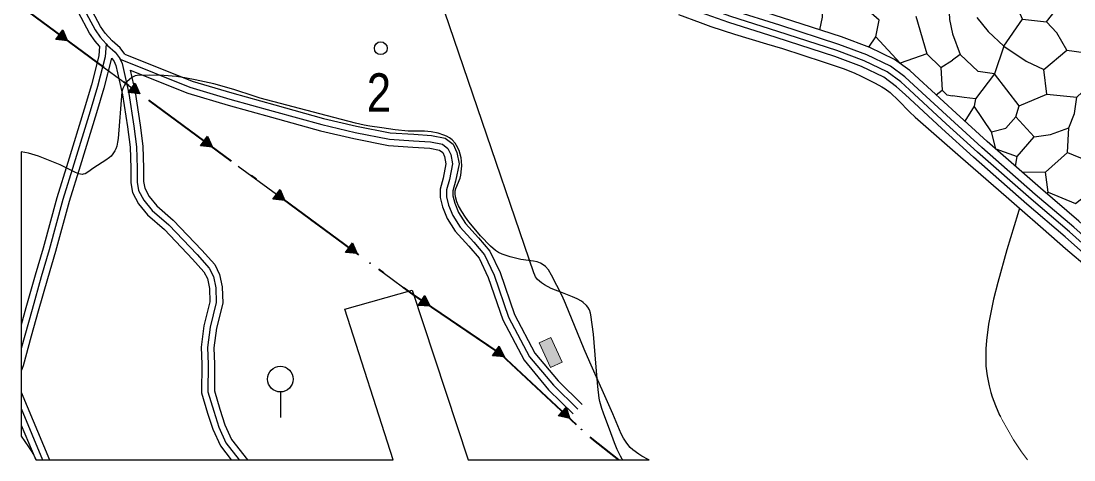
# Model space of a CAD drawing. Extents: x -64005 to -55000, y -89025 to -80000.
# Drawn here: x -64000 to -62360, y -89000 to -88316 of the extents above; entities that cross this region are included whole.
import ezdxf
from ezdxf.enums import TextEntityAlignment as Align

# ---------------------------------------------------------------- set-up
doc = ezdxf.new("R2010")
doc.units = 0
doc.header["$LTSCALE"] = 32
doc.linetypes.add('DOT_DASHED', pattern=[7.7, 5, -1.2, 0.3, -1.2])
doc.linetypes.add('LONG_DASHED', pattern=[7.5, 6, -1.5])
for name, color, linetype, lineweight in [('18', 7, 'Continuous', 25), ('19', 7, 'Continuous', 25), ('2', 7, 'Continuous', 25), ('24', 7, 'Continuous', 25), ('32', 7, 'Continuous', 25), ('39', 7, 'LONG_DASHED', 25), ('52', 7, 'Continuous', 25), ('7', 7, 'Continuous', 13), ('8', 7, 'Continuous', 25)]:
    doc.layers.add(name, color=color, linetype=linetype, lineweight=lineweight)
doc.layers.add('38', color=7, linetype='Continuous')

msp = doc.modelspace()

# ---------------------------------------------------------------- hatches: boundary and pattern name
at = {"layer": '18'}
for points in [[(-63934.92, -88329.93), (-63927.49, -88346.87), (-63945.88, -88344.83)], [(-63822.12, -88412.86), (-63814.69, -88429.8), (-63833.08, -88427.76)], [(-63709.33, -88495.79), (-63701.9, -88512.73), (-63720.29, -88510.69)], [(-63596.53, -88578.72), (-63589.1, -88595.66), (-63607.49, -88593.62)], [(-63483.74, -88661.65), (-63476.31, -88678.59), (-63494.7, -88676.55)], [(-63370.87, -88743.88), (-63362.81, -88760.53), (-63381.26, -88759.18)], [(-63255.05, -88822.53), (-63247, -88839.18), (-63265.44, -88837.83)], [(-63150.56, -88917.65), (-63145.14, -88935.34), (-63163.17, -88931.19)]]:
    msp.add_hatch(color=256, dxfattribs=at).paths.add_polyline_path(points)
at = {"layer": '7'}
msp.add_hatch(color=256, dxfattribs=at).paths.add_polyline_path([(-63192.7, -88817.29), (-63175.05, -88855.95), (-63156.86, -88847.65), (-63174.51, -88808.99)])

# ---------------------------------------------------------------- linework, layer by layer
at = {"layer": '18'}
for p, q in [((-64000, -88293.56), (-63940.4, -88337.38)), ((-63887.21, -88376.49), (-63827.6, -88420.31)), ((-63774.41, -88459.42), (-63714.81, -88503.24)), ((-63661.62, -88542.35), (-63602.01, -88586.17)), ((-63548.82, -88625.28), (-63489.22, -88669.1)), ((-63321.45, -88788.62), (-63260.25, -88830.18)), ((-63210.99, -88873.99), (-63156.86, -88924.42)), ((-63108.18, -88968.98), (-63069.17, -88999.91))]:
    msp.add_line(p, q, dxfattribs=at)
at = {"layer": '18', "linetype": 'DOT_DASHED', "lineweight": 40}
msp.add_lwpolyline([(-64000, -88293.56), (-63389.67, -88742.29), (-63252.06, -88835.74), (-63113.83, -88964.5), (-63069.18, -88999.89)], dxfattribs=at)
at = {"layer": '18'}
for points in [[(-63934.92, -88329.93), (-63927.49, -88346.87), (-63945.88, -88344.83)], [(-63822.12, -88412.86), (-63814.69, -88429.8), (-63833.08, -88427.76)], [(-63709.33, -88495.79), (-63701.9, -88512.73), (-63720.29, -88510.69)], [(-63596.53, -88578.72), (-63589.1, -88595.66), (-63607.49, -88593.62)], [(-63483.74, -88661.65), (-63476.31, -88678.59), (-63494.7, -88676.55)], [(-63370.87, -88743.88), (-63362.81, -88760.53), (-63381.26, -88759.18)], [(-63255.05, -88822.53), (-63247, -88839.18), (-63265.44, -88837.83)], [(-63150.56, -88917.65), (-63145.14, -88935.34), (-63163.17, -88931.19)]]:
    msp.add_lwpolyline(points, close=True, dxfattribs=at)
msp.add_lwpolyline([(-63436.03, -88708.21), (-63389.67, -88742.29), (-63376.07, -88751.53)], dxfattribs=at)
for centre in [(-63907.35, -88361.68), (-63794.55, -88444.61), (-63681.76, -88527.54), (-63568.96, -88610.47), (-63456.17, -88693.4), (-63342.13, -88774.57), (-63229.29, -88856.95), (-63126.85, -88952.37)]:
    msp.add_circle(centre, 0.5, dxfattribs=at)
at = {"layer": '19'}
for p, q in [((-62630.18, -88382.27), (-62630.13, -88382.02)), ((-62574.24, -88430.98), (-62564.94, -88423.87)), ((-62450.68, -88542.48), (-62448.15, -88527.4))]:
    msp.add_line(p, q, dxfattribs=at)
for points in [[(-62553.06, -88239.71), (-62557.03, -88267.02), (-62553.95, -88302.7), (-62553.53, -88313.89), (-62548.89, -88336.1)], [(-62439.78, -88313.28), (-62402.36, -88317.25), (-62377.26, -88285.52), (-62389.15, -88241.03)], [(-62234.98, -88752.06), (-62248.02, -88729.05), (-62267, -88705.72), (-62304.13, -88670.41), (-62351.69, -88627.84), (-62411.55, -88576.82), (-62494.57, -88503.96), (-62543.23, -88459.51), (-62600.48, -88406.83), (-62615.11, -88393.33), (-62638.89, -88375.88), (-62677.57, -88357.31), (-62721.51, -88340.97), (-62813.78, -88310.94), (-62886.97, -88287.85), (-62917.54, -88277.03)], [(-62755.4, -88329.94), (-62751.22, -88310.19), (-62750.79, -88287.28)], [(-62468.85, -88355.14), (-62439.78, -88313.28), (-62455.21, -88276.71)], [(-62370.65, -88361.74), (-62328.82, -88367.47), (-62313.41, -88341.03), (-62337.62, -88285.08)], [(-62679.37, -88356.64), (-62668, -88341.03), (-62663.15, -88314.6), (-62688.26, -88292.58)], [(-62605.92, -88308.43), (-62588.74, -88367.04), (-62566.72, -88388.62), (-62548.89, -88376.89)], [(-62510.68, -88310.64), (-62493.06, -88332.67), (-62468.85, -88355.14), (-62483.38, -88398.31), (-62508.92, -88394.79), (-62536.66, -88368.36)], [(-62468.85, -88355.14), (-62434.06, -88378.48), (-62406.33, -88391.71), (-62370.65, -88361.74), (-62386.08, -88334.44), (-62402.36, -88317.25)], [(-62548.89, -88336.1), (-62536.66, -88368.36), (-62548.89, -88376.89)], [(-62588.74, -88367.04), (-62630.13, -88382.02), (-62668, -88341.03)], [(-62566.72, -88388.62), (-62564.94, -88423.87), (-62557.46, -88431.36), (-62548.89, -88432.62)], [(-62483.38, -88398.31), (-62512.87, -88437.51), (-62530.49, -88435.32), (-62548.89, -88432.62)], [(-62488.22, -88488.62), (-62465.77, -88483.34), (-62449.92, -88465.27), (-62444.64, -88448.52), (-62483.38, -88398.31)], [(-62444.64, -88448.52), (-62401.92, -88430.03), (-62406.33, -88391.71)], [(-62401.92, -88430.03), (-62354.8, -88434.87), (-62320.01, -88401.84)], [(-62449.92, -88465.27), (-62421.72, -88496.55), (-62396.18, -88493.03), (-62367.57, -88482.45), (-62358.75, -88459.99), (-62354.8, -88434.87)], [(-62512.87, -88437.51), (-62515.08, -88448.98), (-62529.3, -88472.24)], [(-62481.79, -88515.17), (-62481.17, -88515.05), (-62488.22, -88488.62), (-62515.08, -88448.98)], [(-62440.72, -88551.22), (-62403.67, -88551.9), (-62369.33, -88521.06), (-62367.57, -88482.45)], [(-62369.33, -88521.06), (-62320.01, -88541.33), (-62323.52, -88476.29)], [(-62481.17, -88515.05), (-62448.15, -88527.4), (-62421.72, -88496.55)], [(-62399.72, -88582.75), (-62357, -88600.37), (-62322.65, -88573.5), (-62320.01, -88541.33)], [(-62401.47, -88585.41), (-62399.72, -88582.75), (-62403.67, -88551.9)]]:
    msp.add_lwpolyline(points, dxfattribs=at)
at = {"layer": '2'}
msp.add_line((-62475.5, -88930), (-62474.07, -88932.55), dxfattribs=at)
for points in [[(-63062.47, -88999.9), (-63063.19, -88998.82), (-63066.05, -88993.88), (-63071.03, -88983.69), (-63075.33, -88973.19), (-63083.18, -88951.8), (-63087.32, -88941.22), (-63092.78, -88927.12), (-63095.2, -88919.99), (-63098.07, -88909.11), (-63099.06, -88903.56), (-63101.32, -88885.48), (-63104.56, -88849.22), (-63108.22, -88804.04), (-63112.27, -88773.7), (-63112.75, -88771.08), (-63114.41, -88766.27), (-63116.91, -88762), (-63119, -88759.42), (-63124.09, -88754.81), (-63127.02, -88752.75), (-63133.55, -88749.02), (-63140.75, -88745.7), (-63156.35, -88739.72), (-63173.96, -88732.85), (-63184.54, -88727.41), (-63189.22, -88724.25), (-63195.19, -88718.8), (-63198.34, -88714.6), (-63199.64, -88712.31), (-63201.2, -88708.61), (-63391.24, -88151.2)], [(-62444.21, -88607.9), (-62447.06, -88616.58), (-62452.9, -88635.23), (-62463.9, -88672.77), (-62478.38, -88723.63), (-62484.82, -88749.43), (-62490.25, -88775.31), (-62492.47, -88788.24), (-62495.69, -88814.01), (-62496.6, -88826.83), (-62496.96, -88845.91), (-62496.65, -88853.66), (-62494.92, -88869.13), (-62491.81, -88884.53), (-62489.03, -88894.74), (-62486.88, -88901.51), (-62481.92, -88914.96), (-62475.5, -88930)]]:
    msp.add_lwpolyline(points, dxfattribs=at)
at = {"layer": '2', "lineweight": 13}
msp.add_lwpolyline([(-62431.67, -89000), (-62441.18, -88987.24), (-62453.74, -88968.67), (-62471.19, -88937.69), (-62474.07, -88932.55)], dxfattribs=at)
at = {"layer": '24'}
msp.add_line((-63303.49, -88999.93), (-63021.53, -88999.9), dxfattribs=at)
for points in [[(-63021.53, -88999.9), (-63022.89, -88999.24), (-63032.86, -88993.92), (-63037.65, -88990.99), (-63046.63, -88984.34), (-63050.75, -88980.52), (-63056.36, -88974.04), (-63061.58, -88966.04), (-63065.04, -88959.37), (-63077.81, -88928.3), (-63114.03, -88847.78), (-63122.67, -88827.58), (-63151.67, -88756.3), (-63157.18, -88744.24), (-63173.56, -88711.97), (-63178.38, -88703.7), (-63183.01, -88698.36), (-63184.83, -88696.83), (-63190.54, -88693.52), (-63195.99, -88691.57), (-63201.57, -88690.33), (-63221.37, -88687.71), (-63237.91, -88683.47), (-63250.16, -88679.46), (-63255.86, -88676.81), (-63260.88, -88673.61), (-63268.45, -88667.18), (-63283.92, -88651.02), (-63294.25, -88639.05), (-63302.23, -88629.1), (-63307.48, -88621.99), (-63313.43, -88612.81), (-63318.43, -88603.85), (-63321.16, -88597.7), (-63323.25, -88589.86), (-63323.7, -88585.19), (-63323.46, -88580.9), (-63322.49, -88576.95), (-63315.86, -88561.22), (-63314.62, -88556.2), (-63313.62, -88546.52), (-63313.43, -88541.61), (-63313.67, -88534.28), (-63314.29, -88529.42), (-63315.66, -88523.43), (-63317.48, -88518.08), (-63321.39, -88510.1), (-63323.87, -88506.48), (-63328.44, -88501.41), (-63332.42, -88498.16), (-63337.17, -88495.42), (-63341.3, -88493.78), (-63350.12, -88491.14), (-63361.21, -88488.73), (-63371.32, -88487.59), (-63396.75, -88487.82), (-63416.88, -88485.79), (-63438.03, -88482.83), (-63456.34, -88479.85), (-63465.45, -88478.2), (-63479.01, -88475.22), (-63534.28, -88460.94), (-63627.68, -88436.18), (-63636.85, -88433.45), (-63668.65, -88422.84), (-63699.62, -88414.27), (-63728.69, -88407.6), (-63744.9, -88404.58), (-63758, -88402.81), (-63777.79, -88401.13), (-63799.81, -88400.54), (-63818.97, -88401.08), (-63822.19, -88401.77), (-63825.28, -88403.01), (-63827.28, -88404.15), (-63831.14, -88407.14), (-63835.04, -88411.08), (-63839.01, -88416.24), (-63841.61, -88421.16)], [(-63841.61, -88421.16), (-63843.17, -88426.4), (-63848.74, -88499.1), (-63849.51, -88505.03), (-63850.76, -88510.93), (-63852.22, -88515.53), (-63853.66, -88518.64), (-63856.75, -88523.28), (-63859.74, -88526.6), (-63862.25, -88528.89), (-63867.79, -88533.11), (-63886.42, -88544.85), (-63895.71, -88551.51), (-63900.36, -88554.07), (-63903.47, -88554.99), (-63905.03, -88555.13), (-63907.37, -88554.86), (-63910.01, -88554.12), (-63915.3, -88552.17), (-63920.59, -88549.76), (-63939.12, -88540.36), (-63972.92, -88526.68), (-63983.16, -88523.34), (-63988.37, -88521.99), (-64000, -88519.92), (-64000, -88963.07)], [(-63495.73, -88765.19), (-63390.7, -88735.39), (-63303.49, -88999.93)], [(-64000, -88963.07), (-63988.26, -88979.59), (-63983.2, -88987.26), (-63980.12, -88992.55), (-63976.3, -89000), (-63420.42, -88999.94), (-63495.73, -88765.19)]]:
    msp.add_lwpolyline(points, dxfattribs=at)
at = {"layer": '32'}
msp.add_line((-63596.01, -88894.13), (-63596.01, -88934.13), dxfattribs=at)
msp.add_circle((-63596.01, -88874.13), 20, dxfattribs=at)
at = {"layer": '39'}
msp.add_line((-64000, -88920.07), (-63966.34, -89000), dxfattribs=at)
for points in [[(-63742.17, -87961.4), (-63771.59, -88028.32), (-63794.08, -88059.15), (-63833.98, -88124.09), (-63848.48, -88135.71), (-63866.98, -88144.05), (-63886.56, -88150.94), (-63897.8, -88157.11), (-63904.69, -88164.01), (-63909.77, -88181.89), (-63918.47, -88201.12), (-63928.58, -88217.4), (-63933.71, -88230.13), (-63932.99, -88241.39), (-63914.12, -88273.67), (-63901.79, -88298.34), (-63884.75, -88329.9), (-63876.77, -88341.49), (-63867.63, -88351.49)], [(-62243.87, -88781.4), (-62248.75, -88773.41), (-62266.67, -88741.78), (-62283.54, -88721.04), (-62319.4, -88686.95), (-62366.5, -88644.79), (-62426.26, -88593.83), (-62509.58, -88520.73), (-62558.44, -88476.09), (-62615.73, -88423.38), (-62629.44, -88410.73), (-62650.52, -88395.26), (-62686.39, -88378.04), (-62728.92, -88362.23), (-62820.65, -88332.36), (-62894.12, -88309.19), (-62932.2, -88295.7)], [(-63867.63, -88351.49), (-63868.79, -88372.09), (-63880.81, -88418.23), (-63892.19, -88456.57), (-63917.52, -88539.41), (-63934.73, -88594.33), (-63956.18, -88672.63), (-63968.53, -88714.86), (-63982.83, -88765.55), (-64000, -88826.13)], [(-63867.63, -88351.49), (-63865.16, -88354.19), (-63853.2, -88364.71), (-63847.03, -88373.05), (-63845.83, -88375.65)], [(-63845.83, -88375.65), (-63736.89, -88419.23), (-63674.54, -88437.85), (-63607.34, -88456.48), (-63531.22, -88477.52), (-63479.4, -88489.66), (-63425.96, -88500.18), (-63388.71, -88502.61), (-63361.99, -88504.22), (-63343.57, -88508.07), (-63335.06, -88514.54), (-63330.61, -88524.26), (-63327.77, -88538.43), (-63332.63, -88563.13), (-63337.09, -88579.33), (-63337.09, -88589.86), (-63333.85, -88602.82), (-63327.37, -88619.01), (-63315.64, -88637.47), (-63294.58, -88660.56), (-63277.98, -88680.4), (-63263.01, -88712), (-63240.33, -88777.62), (-63207.93, -88839.19), (-63170.68, -88883.73), (-63132.62, -88921)], [(-63845.83, -88375.65), (-63842.68, -88382.48), (-63832.16, -88429.02), (-63824.19, -88479.81), (-63820.2, -88512.1), (-63819.11, -88545.47), (-63819.11, -88567.23), (-63816.93, -88580.04), (-63808.58, -88595.27), (-63795.89, -88611.23), (-63769.78, -88633.72), (-63725.54, -88680.15), (-63706.68, -88701.18), (-63700.15, -88714.24), (-63696.53, -88731.65), (-63695.8, -88754.5), (-63705.23, -88793.06), (-63709.58, -88824.99), (-63708.49, -88850.74), (-63708.86, -88893.91), (-63699.79, -88924.02), (-63691.81, -88948.68), (-63680.82, -88973.09), (-63660.07, -88999.97)]]:
    msp.add_lwpolyline(points, dxfattribs=at)
at = {"layer": '52'}
msp.add_circle((-63439.56, -88358.53), 10, dxfattribs=at)
at = {"layer": '7', "lineweight": 25}
for points in [[(-62975.75, -88305.79), (-62942.11, -88318.47), (-62925.18, -88324.53), (-62888.21, -88336.56), (-62838.57, -88351.54), (-62813.8, -88359.18), (-62750.47, -88379.73), (-62718.9, -88390.37), (-62702.07, -88396.96), (-62691.12, -88402), (-62669.5, -88412.89), (-62658.66, -88418.79), (-62653.45, -88422.06), (-62646.09, -88427.63), (-62632.85, -88440.16), (-62615.92, -88457.49), (-62607.09, -88465.77), (-62536.44, -88527.73), (-62464.93, -88589.7), (-62444.21, -88607.9)], [(-62444.21, -88607.9), (-62407.73, -88639.95), (-62372.63, -88670.72), (-62335.79, -88701.92), (-62315.56, -88720.32), (-62305.89, -88730.06), (-62296.04, -88741.24), (-62289.98, -88749.1), (-62279.01, -88765.6), (-62241.31, -88830.17), (-62215.54, -88872.48), (-62202.31, -88893.44), (-62188.89, -88913.21), (-62160.28, -88951.51), (-62137.47, -88980.96), (-62125.59, -88995.26), (-62121.48, -88999.8)]]:
    msp.add_lwpolyline(points, dxfattribs=at)
at = {"layer": '7'}
msp.add_lwpolyline([(-63192.7, -88817.29), (-63175.05, -88855.95), (-63156.86, -88847.65), (-63174.51, -88808.99)], close=True, dxfattribs=at)
at = {"layer": '8'}
msp.add_line((-64000, -88894.3), (-63955.49, -89000), dxfattribs=at)
at = {"layer": '8', "linetype": 'LONG_DASHED'}
msp.add_line((-64000, -88945.84), (-63977.2, -88999.99), dxfattribs=at)
for points in [[(-63877.85, -88355.14), (-63884.62, -88347.74), (-63893.29, -88335.12), (-63910.66, -88302.95), (-63922.93, -88278.43), (-63942.82, -88244.39), (-63943.58, -88232.63), (-63943.8, -88229.13), (-63937.16, -88212.43), (-63927.14, -88196.01), (-63919.19, -88178.44), (-63913.6, -88158.78), (-63903.86, -88149.04), (-63890.65, -88141.78), (-63870.7, -88134.76), (-63853.74, -88127.11), (-63841.59, -88117.37), (-63802.39, -88053.58), (-63780.31, -88023.3), (-63754.33, -87964.27)], [(-62326.18, -88694.3), (-62373.08, -88652.32), (-62432.8, -88601.39), (-62516.25, -88528.18), (-62565.2, -88483.46), (-62622.51, -88430.73), (-62635.81, -88418.46), (-62655.69, -88403.87), (-62690.31, -88387.25), (-62732.21, -88371.67), (-62823.7, -88341.88), (-62897.3, -88318.67), (-62959.02, -88296.81), (-63072.59, -88255.33), (-63169.31, -88220.17), (-63237.92, -88194.15), (-63302.6, -88169.53), (-63475.47, -88103.51), (-63544.26, -88078.6), (-63599.51, -88058.91), (-63682.38, -88027.75), (-63707.53, -88014.79), (-63725.47, -87996.47), (-63739.33, -87979.74)], [(-63877.85, -88355.14), (-63878.72, -88370.53), (-63890.44, -88415.55), (-63901.77, -88453.69), (-63927.07, -88536.46), (-63944.33, -88591.51), (-63965.8, -88669.91), (-63978.14, -88712.11), (-63992.46, -88762.83), (-64000, -88789.45)], [(-63838.46, -88367.83), (-63733.59, -88409.78), (-63671.77, -88428.24), (-63604.67, -88446.83), (-63528.74, -88467.83), (-63477.29, -88479.88), (-63424.65, -88490.24), (-63388.08, -88492.63), (-63360.66, -88494.28), (-63339.31, -88498.74), (-63327, -88508.12)], [(-63858.91, -88373.81), (-63855.68, -88378.17), (-63852.2, -88385.71), (-63841.99, -88430.91), (-63834.09, -88481.2), (-63830.18, -88512.88), (-63829.11, -88545.63), (-63829.11, -88568.07), (-63826.5, -88583.37), (-63816.94, -88600.82), (-63803.13, -88618.19), (-63776.68, -88640.98), (-63732.88, -88686.94), (-63715.02, -88706.85), (-63709.68, -88717.55), (-63706.5, -88732.84), (-63705.84, -88753.45), (-63715.07, -88791.19), (-63719.61, -88824.52), (-63718.49, -88850.91), (-63718.87, -88895.34), (-63709.34, -88927), (-63701.15, -88952.28), (-63689.45, -88978.27), (-63672.7, -88999.97)], [(-63347.84, -88517.39), (-63343.11, -88520.98), (-63340.19, -88527.37), (-63337.97, -88538.45), (-63342.37, -88560.84), (-63347.09, -88577.98), (-63347.09, -88591.09), (-63343.39, -88605.9), (-63336.31, -88623.59), (-63323.61, -88643.57), (-63302.11, -88667.14), (-63286.47, -88685.85), (-63272.28, -88715.79), (-63249.53, -88781.6), (-63216.29, -88844.79), (-63178.03, -88890.54), (-63139.61, -88928.14)]]:
    msp.add_lwpolyline(points, dxfattribs=at)
at = {"layer": '8'}
for points in [[(-63838.46, -88367.83), (-63845.79, -88357.91), (-63858.15, -88347.04), (-63868.92, -88335.25), (-63876.21, -88324.67), (-63892.92, -88293.72), (-63905.32, -88268.9), (-63923.15, -88238.38), (-63923.56, -88231.92), (-63923.61, -88231.14), (-63919.26, -88221.87), (-63909.8, -88206.23), (-63900.35, -88185.34), (-63895.78, -88169.24), (-63891.74, -88165.19), (-63882.47, -88160.1), (-63863.26, -88153.34), (-63843.22, -88144.31), (-63826.37, -88130.81), (-63785.77, -88064.72), (-63762.87, -88033.34), (-63739.33, -87979.74)], [(-62240.22, -88768.19), (-62258.38, -88736.12), (-62276.19, -88714.23), (-62312.62, -88679.6), (-62359.92, -88637.26), (-62419.72, -88586.27), (-62502.91, -88513.28), (-62551.68, -88468.72), (-62608.95, -88416.02), (-62623.07, -88403), (-62645.35, -88386.65), (-62682.47, -88368.83), (-62725.63, -88352.79), (-62817.6, -88322.84), (-62890.94, -88299.7), (-62926.19, -88287.22)], [(-63858.91, -88373.81), (-63871.18, -88420.91), (-63882.6, -88459.44), (-63907.97, -88542.37), (-63925.13, -88597.15), (-63946.56, -88675.35), (-63958.92, -88717.62), (-63973.21, -88768.27), (-63984.24, -88807.21), (-63996.78, -88853.37), (-63999.08, -88859.9)], [(-63830.12, -88392.7), (-63740.19, -88428.68), (-63677.31, -88447.46), (-63610.01, -88466.12), (-63533.7, -88487.21), (-63481.51, -88499.44), (-63427.26, -88510.12), (-63389.34, -88512.59), (-63363.32, -88514.17), (-63347.84, -88517.39)], [(-63830.12, -88392.7), (-63822.33, -88427.14), (-63814.29, -88478.42), (-63810.22, -88511.32), (-63809.11, -88545.31), (-63809.11, -88566.39), (-63807.35, -88576.71), (-63800.23, -88589.72), (-63788.65, -88604.27), (-63762.88, -88626.46), (-63718.2, -88673.36), (-63698.34, -88695.5), (-63690.61, -88710.92), (-63686.55, -88730.46), (-63685.76, -88755.55), (-63695.39, -88794.93), (-63699.55, -88825.45), (-63698.49, -88850.57), (-63698.85, -88892.48), (-63690.24, -88921.04), (-63682.47, -88945.08), (-63672.19, -88967.91), (-63647.44, -88999.96)], [(-63327, -88508.12), (-63321.03, -88521.15), (-63317.57, -88538.41), (-63322.89, -88565.43), (-63327.09, -88580.67), (-63327.09, -88588.63), (-63324.31, -88599.74), (-63318.43, -88614.43), (-63307.67, -88631.37), (-63287.05, -88653.97), (-63269.49, -88674.96), (-63253.74, -88708.2), (-63231.13, -88773.63), (-63199.58, -88833.58), (-63163.33, -88876.93), (-63125.62, -88913.85)]]:
    msp.add_lwpolyline(points, dxfattribs=at)

# ---------------------------------------------------------------- texts
at = {"layer": '38', "width": 0.85}
msp.add_text('2', height=60, rotation=0.008, dxfattribs=at).set_placement((-63442.41, -88457.62), align=Align.CENTER)

doc.saveas('drawing.dxf')
